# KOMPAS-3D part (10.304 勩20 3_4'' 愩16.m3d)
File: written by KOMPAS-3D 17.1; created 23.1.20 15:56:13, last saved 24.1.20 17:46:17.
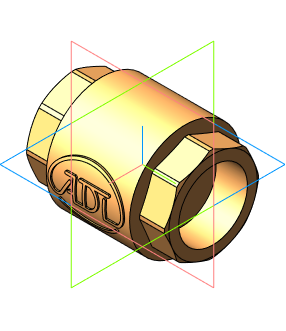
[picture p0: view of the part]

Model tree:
1. Операция без истории:2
